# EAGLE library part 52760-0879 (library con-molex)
MOLEX Connector SD-52760-**79 Source: 52760-1079_sd molex.pdf
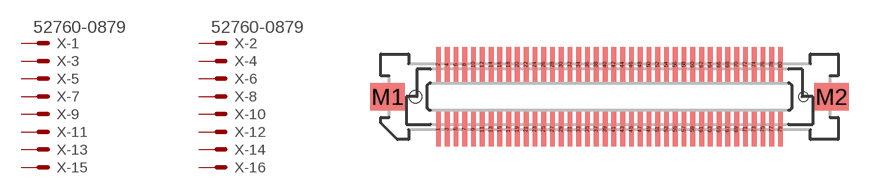
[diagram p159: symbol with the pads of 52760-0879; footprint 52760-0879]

Designator prefix X; gates -1=MV -2=MV -3=M -4=M -5=M -6=M -7=M -8=M -9=M -10=M -11=M -12=M -13=M -14=M -15=M -16=M -17=M -18=M -19=M -20=M -21=M -22=M -23=M -24=M -25=M -26=M -27=M -28=M -29=M -30=M -31=M -32=M -33=M -34=M -35=M -36=M -37=M -38=M -39=M -40=M -41=M -42=M -43=M -44=M -45=M -46=M -47=M -48=M -49=M -50=M -51=M -52=M -53=M -54=M -55=M -56=M -57=M -58=M -59=M -60=M -61=M -62=M -63=M -64=M -65=M -66=M -67=M -68=M -69=M -70=M -71=M -72=M -73=M -74=M -75=M -76=M -77=M -78=M -79=M -80=M

## 52760-0879 (OC_FARNELL: unknown; OC_NEWARK: unknown)  [52760-0879]
1  -1:S  pas
2  -2:S  pas
3  -3:S  pas
4  -4:S  pas
5  -5:S  pas
6  -6:S  pas
7  -7:S  pas
8  -8:S  pas
9  -9:S  pas
10  -10:S  pas
11  -11:S  pas
12  -12:S  pas
13  -13:S  pas
14  -14:S  pas
15  -15:S  pas
16  -16:S  pas
17  -17:S  pas
18  -18:S  pas
19  -19:S  pas
20  -20:S  pas
21  -21:S  pas
22  -22:S  pas
23  -23:S  pas
24  -24:S  pas
25  -25:S  pas
26  -26:S  pas
27  -27:S  pas
28  -28:S  pas
29  -29:S  pas
30  -30:S  pas
31  -31:S  pas
32  -32:S  pas
33  -33:S  pas
34  -34:S  pas
35  -35:S  pas
36  -36:S  pas
37  -37:S  pas
38  -38:S  pas
39  -39:S  pas
40  -40:S  pas
41  -41:S  pas
42  -42:S  pas
43  -43:S  pas
44  -44:S  pas
45  -45:S  pas
46  -46:S  pas
47  -47:S  pas
48  -48:S  pas
49  -49:S  pas
50  -50:S  pas
51  -51:S  pas
52  -52:S  pas
53  -53:S  pas
54  -54:S  pas
55  -55:S  pas
56  -56:S  pas
57  -57:S  pas
58  -58:S  pas
59  -59:S  pas
60  -60:S  pas
61  -61:S  pas
62  -62:S  pas
63  -63:S  pas
64  -64:S  pas
65  -65:S  pas
66  -66:S  pas
67  -67:S  pas
68  -68:S  pas
69  -69:S  pas
70  -70:S  pas
71  -71:S  pas
72  -72:S  pas
73  -73:S  pas
74  -74:S  pas
75  -75:S  pas
76  -76:S  pas
77  -77:S  pas
78  -78:S  pas
79  -79:S  pas
80  -80:S  pas

## Footprint 52760-0879 (pad centres in mm)
MOLEX Connector SD-52760-**79 Source: 52760-1079_sd molex.pdf
smd 0.35 x 2.5: 1 -12.383,-2.35; 2 -12.383,2.35; 3 -11.748,-2.35; 4 -11.748,2.35; 5 -11.113,-2.35; 6 -11.113,2.35; 7 -10.477,-2.35; 8 -10.477,2.35; 9 -9.842,-2.35; 10 -9.842,2.35; 11 -9.207,-2.35; 12 -9.207,2.35; 13 -8.572,-2.35; 14 -8.572,2.35; 15 -7.938,-2.35; 16 -7.938,2.35; 17 -7.303,-2.35; 18 -7.303,2.35; 19 -6.668,-2.35; 20 -6.668,2.35; 21 -6.032,-2.35; 22 -6.032,2.35; 23 -5.397,-2.35; 24 -5.397,2.35; 25 -4.763,-2.35; 26 -4.763,2.35; 27 -4.128,-2.35; 28 -4.128,2.35; 29 -3.493,-2.35; 30 -3.493,2.35; 31 -2.857,-2.35; 32 -2.857,2.35; 33 -2.223,-2.35; 34 -2.223,2.35; 35 -1.587,-2.35; 36 -1.587,2.35; 37 -0.953,-2.35; 38 -0.953,2.35; 39 -0.318,-2.35; 40 -0.318,2.35; 41 0.318,-2.35; 42 0.318,2.35; 43 0.953,-2.35; 44 0.953,2.35; 45 1.587,-2.35; 46 1.587,2.35; 47 2.223,-2.35; 48 2.223,2.35; 49 2.857,-2.35; 50 2.857,2.35; 51 3.493,-2.35; 52 3.493,2.35; 53 4.128,-2.35; 54 4.128,2.35; 55 4.763,-2.35; 56 4.763,2.35; 57 5.397,-2.35; 58 5.397,2.35; 59 6.032,-2.35; 60 6.032,2.35; 61 6.668,-2.35; 62 6.668,2.35; 63 7.303,-2.35; 64 7.303,2.35; 65 7.938,-2.35; 66 7.938,2.35; 67 8.572,-2.35; 68 8.572,2.35; 69 9.207,-2.35; 70 9.207,2.35; 71 9.842,-2.35; 72 9.842,2.35; 73 10.477,-2.35; 74 10.477,2.35; 75 11.113,-2.35; 76 11.113,2.35; 77 11.748,-2.35; 78 11.748,2.35; 79 12.383,-2.35; 80 12.383,2.35
smd 2.5 x 2: M1 -16.075,0; M2 16.075,0
hole 0.9 at -14.035,0
hole 0.7 at 14.035,0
